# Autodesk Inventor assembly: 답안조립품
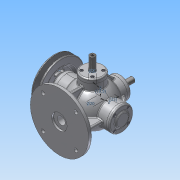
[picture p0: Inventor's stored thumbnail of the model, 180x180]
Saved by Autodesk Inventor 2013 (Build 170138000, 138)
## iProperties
Created: 2016-07
Part Number: 답안조립품
Document SubType Name: Weldment
Designer: Administrator
Weld Material: Welded Aluminum-6061
Author: Administrator
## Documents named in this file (17)
- C:\Users\Administrator\Desktop\360708V1013\답안조립품.iam
- C:\Users\Administrator\Desktop\360708V1013\본체.ipt
- C:\Users\Administrator\Desktop\360708V1013\본체커버.ipt
- C:\Users\Administrator\Desktop\360708V1013\베어링- 6202.ipt
- C:\Users\Administrator\Desktop\360708V1013\뒤커버.ipt
- C:\Users\Administrator\Desktop\360708V1013\앞커버.ipt
- C:\Users\Administrator\Desktop\360708V1013\오일실.ipt
- C:\Users\Administrator\Desktop\360708V1013\축.ipt
- C:\Users\Administrator\Desktop\360708V1013\슬라이드.ipt
- C:\Users\Administrator\Desktop\360708V1013\슬라이드 커버.ipt
- C:\Users\Administrator\Desktop\360708V1013\스프링1.ipt
- C:\Users\Administrator\Desktop\360708V1013\키-4x4.ipt
- C:\Users\Administrator\Desktop\360708V1013\스프링2.ipt
- C:\Users\Administrator\Desktop\360708V1013\볼트 M4x0.7.ipt
- C:\Users\Administrator\Desktop\360708V1013\와셔 8x17.ipt
- C:\Users\Administrator\Desktop\360708V1013\너트-M8x1.ipt
- C:\Users\Administrator\Desktop\360708V1013\V-벨트풀리.ipt
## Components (18 placed, 2 different names)
1. V-벨트풀리:1
2. M4x0.7x12:25
3. M4x0.7x12:9
4. M4x0.7x12:10
5. M4x0.7x12:11
6. M4x0.7x12:12
7. M4x0.7x12:13
8. M4x0.7x12:16
9. M4x0.7x12:17
10. M4x0.7x12:18
11. M4x0.7x12:14
12. M4x0.7x12:19
13. M4x0.7x12:20
14. M4x0.7x12:21
15. M4x0.7x12:15
16. M4x0.7x12:22
17. M4x0.7x12:23
18. M4x0.7x12:24
